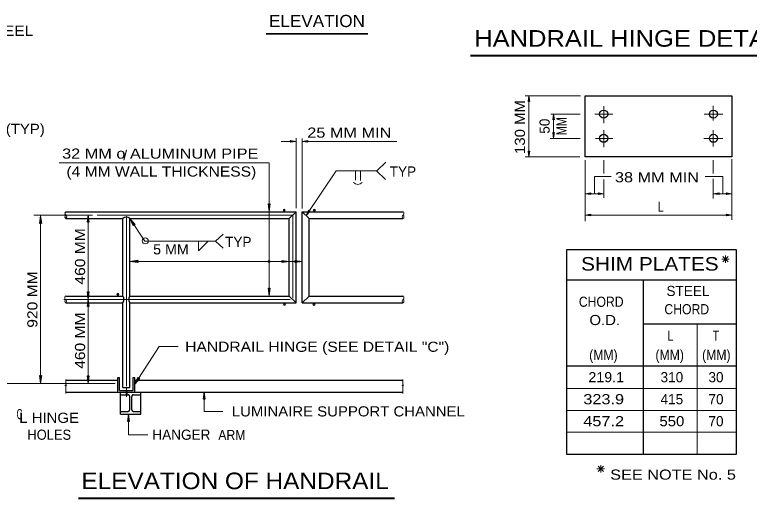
# Model space of a CAD drawing. Extents: x 312601.858 to 312602.699, y 144420.109 to 144420.704.
# Drawn here: x 312602.2633 to 312602.4805, y 144420.41 to 144420.553 of the extents above; entities that cross this region are included whole.
import ezdxf
from ezdxf.enums import TextEntityAlignment as Align

# ---------------------------------------------------------------- set-up
doc = ezdxf.new("R2010")
doc.units = 0
doc.header["$LTSCALE"] = 0.0012
doc.header["$PDMODE"] = 32
doc.header["$PDSIZE"] = 0.0006
doc.linetypes.add('DOT_DASHED', pattern=[7.7, 5, -1.2, 0.3, -1.2])
doc.linetypes.add('MEDIUM_DASHED', pattern=[4.5, 3, -1.5])
for name, color, linetype, lineweight in [('1', 7, 'Continuous', 13), ('2', 7, 'Continuous', 13), ('39', 7, 'Continuous', 13)]:
    doc.layers.add(name, color=color, linetype=linetype, lineweight=lineweight)

msp = doc.modelspace()

# ---------------------------------------------------------------- hatches: boundary and pattern name
at = {"layer": '2'}
msp.add_hatch(color=256, dxfattribs=at).paths.add_polyline_path([(312602.3388, 144420.48, 1), (312602.3382, 144420.48, 1)])
at = {"layer": '39'}
for points in [[(312602.4153, 144420.5275), (312602.4151, 144420.5273), (312602.4153, 144420.529), (312602.4156, 144420.5273)], [(312602.4153, 144420.5275), (312602.4151, 144420.5273), (312602.4153, 144420.529), (312602.4156, 144420.5273)], [(312602.4226, 144420.5221), (312602.4224, 144420.5219), (312602.4226, 144420.5236), (312602.4229, 144420.5219)], [(312602.4226, 144420.518), (312602.4229, 144420.5181), (312602.4226, 144420.5164), (312602.4224, 144420.5181)], [(312602.4226, 144420.518), (312602.4229, 144420.5181), (312602.4226, 144420.5164), (312602.4224, 144420.5181)], [(312602.345, 144420.5155), (312602.3448, 144420.5158), (312602.3465, 144420.5155), (312602.3448, 144420.5153)], [(312602.3499, 144420.5155), (312602.35, 144420.5153), (312602.3483, 144420.5155), (312602.35, 144420.5158)], [(312602.4153, 144420.5125), (312602.4156, 144420.5126), (312602.4153, 144420.5109), (312602.4151, 144420.5126)], [(312602.4153, 144420.5125), (312602.4156, 144420.5126), (312602.4153, 144420.5109), (312602.4151, 144420.5126)], [(312602.4336, 144420.5), (312602.4337, 144420.4998), (312602.432, 144420.5), (312602.4337, 144420.5003)], [(312602.436, 144420.5), (312602.4358, 144420.5003), (312602.4375, 144420.5), (312602.4358, 144420.4998)], [(312602.436, 144420.5), (312602.4358, 144420.5003), (312602.4375, 144420.5), (312602.4358, 144420.4998)], [(312602.4715, 144420.5), (312602.4716, 144420.4998), (312602.4699, 144420.5), (312602.4716, 144420.5003)], [(312602.4739, 144420.5), (312602.4737, 144420.5003), (312602.4754, 144420.5), (312602.4737, 144420.4998)], [(312602.3504, 144420.4949), (312602.3507, 144420.4949), (312602.3495, 144420.4936), (312602.3502, 144420.4952)], [(312602.2709, 144420.4914), (312602.2706, 144420.4912), (312602.2709, 144420.4936), (312602.2713, 144420.4912)], [(312602.2709, 144420.4914), (312602.2706, 144420.4912), (312602.2709, 144420.4936), (312602.2713, 144420.4912)], [(312602.2985, 144420.4909), (312602.2983, 144420.4905), (312602.2973, 144420.4927), (312602.2989, 144420.4909)], [(312602.4336, 144420.4937), (312602.4337, 144420.4935), (312602.432, 144420.4937), (312602.4337, 144420.494)], [(312602.4739, 144420.4937), (312602.4737, 144420.494), (312602.4754, 144420.4937), (312602.4737, 144420.4935)], [(312602.2995, 144420.48), (312602.2997, 144420.4797), (312602.2973, 144420.48), (312602.2997, 144420.4804)], [(312602.2996, 144420.48), (312602.2998, 144420.4797), (312602.2974, 144420.48), (312602.2998, 144420.4804)], [(312602.2709, 144420.4461), (312602.2713, 144420.4463), (312602.2709, 144420.4439), (312602.2706, 144420.4463)]]:
    msp.add_hatch(color=256, dxfattribs=at).paths.add_polyline_path(points)

# ---------------------------------------------------------------- linework, layer by layer
at = {"layer": '1'}
for p, q in [((312602.4143, 144420.529), (312602.4306, 144420.529)), ((312602.4153, 144420.529), (312602.4153, 144420.5109)), ((312602.4218, 144420.5236), (312602.4305, 144420.5236)), ((312602.4226, 144420.5236), (312602.4226, 144420.5164)), ((312602.3465, 144420.4958), (312602.3465, 144420.5165)), ((312602.3483, 144420.4957), (312602.3483, 144420.5164)), ((312602.4217, 144420.5164), (312602.4305, 144420.5164)), ((312602.3421, 144420.5155), (312602.3465, 144420.5155)), ((312602.3483, 144420.5155), (312602.3763, 144420.5155)), ((312602.4304, 144420.5109), (312602.4143, 144420.5109)), ((312602.432, 144420.4919), (312602.432, 144420.51)), ((312602.4375, 144420.51), (312602.4375, 144420.506)), ((312602.4699, 144420.51), (312602.4699, 144420.506)), ((312602.4754, 144420.5102), (312602.4754, 144420.4923)), ((312602.2764, 144420.5092), (312602.3385, 144420.5092)), ((312602.3385, 144420.5092), (312602.3385, 144420.4947)), ((312602.3641, 144420.504), (312602.3641, 144420.5068)), ((312602.3656, 144420.5039), (312602.3656, 144420.5068)), ((312602.4375, 144420.5042), (312602.4375, 144420.4988)), ((312602.4699, 144420.5044), (312602.4699, 144420.4986)), ((312602.432, 144420.5), (312602.4375, 144420.5)), ((312602.4699, 144420.5), (312602.4754, 144420.5)), ((312602.3385, 144420.4947), (312602.3385, 144420.4698)), ((312602.2689, 144420.4937), (312602.2863, 144420.4937)), ((312602.2709, 144420.4936), (312602.2709, 144420.4439)), ((312602.285, 144420.4937), (312602.285, 144420.4439)), ((312602.432, 144420.4937), (312602.4754, 144420.4937)), ((312602.4651, 144420.4616), (312602.4651, 144420.4229)), ((312602.2988, 144420.4437), (312602.306, 144420.4549)), ((312602.306, 144420.4549), (312602.3116, 144420.4549)), ((312602.254, 144420.4439), (312602.293, 144420.4439)), ((312602.4767, 144420.4425), (312602.4266, 144420.4425)), ((312602.2969, 144420.4349), (312602.2969, 144420.4288)), ((312602.4767, 144420.436), (312602.4266, 144420.436)), ((312602.4767, 144420.4295), (312602.4266, 144420.4295)), ((312602.3027, 144420.4288), (312602.2969, 144420.4288))]:
    msp.add_line(p, q, dxfattribs=at)
at = {"layer": '1', "lineweight": 25}
for p, q in [((312602.432, 144420.529), (312602.4754, 144420.529)), ((312602.432, 144420.5109), (312602.432, 144420.529)), ((312602.4754, 144420.529), (312602.4754, 144420.5109)), ((312602.4754, 144420.5109), (312602.432, 144420.5109)), ((312602.2784, 144420.4947), (312602.2938, 144420.4947)), ((312602.2937, 144420.4947), (312602.3465, 144420.4947)), ((312602.3465, 144420.4678), (312602.3465, 144420.4947)), ((312602.3483, 144420.4947), (312602.3781, 144420.4947)), ((312602.3483, 144420.4678), (312602.3483, 144420.4947)), ((312602.2784, 144420.4927), (312602.2953, 144420.4927)), ((312602.2953, 144420.4698), (312602.2953, 144420.4927)), ((312602.2973, 144420.4927), (312602.3445, 144420.4927)), ((312602.2973, 144420.4698), (312602.2973, 144420.4927)), ((312602.3445, 144420.4698), (312602.3445, 144420.4927)), ((312602.3504, 144420.4927), (312602.3781, 144420.4927)), ((312602.3504, 144420.4698), (312602.3504, 144420.4927)), ((312602.4266, 144420.4835), (312602.4767, 144420.4835)), ((312602.4266, 144420.4229), (312602.4266, 144420.4835)), ((312602.4266, 144420.4746), (312602.4767, 144420.4746)), ((312602.4492, 144420.4746), (312602.4492, 144420.4229)), ((312602.2784, 144420.4698), (312602.2953, 144420.4698)), ((312602.2973, 144420.4698), (312602.3445, 144420.4698)), ((312602.3504, 144420.4698), (312602.3781, 144420.4698)), ((312602.2784, 144420.4678), (312602.2953, 144420.4678)), ((312602.2953, 144420.4428), (312602.2953, 144420.4678)), ((312602.2973, 144420.4678), (312602.3465, 144420.4678)), ((312602.2973, 144420.4428), (312602.2973, 144420.4678)), ((312602.3483, 144420.4678), (312602.3781, 144420.4678)), ((312602.4492, 144420.4616), (312602.4767, 144420.4616)), ((312602.4266, 144420.4492), (312602.4767, 144420.4492)), ((312602.2784, 144420.4449), (312602.2938, 144420.4449)), ((312602.2938, 144420.4457), (312602.2943, 144420.4457)), ((312602.2938, 144420.4414), (312602.2938, 144420.4457)), ((312602.2943, 144420.4419), (312602.2943, 144420.4457)), ((312602.2983, 144420.4457), (312602.2988, 144420.4457)), ((312602.2983, 144420.4419), (312602.2983, 144420.4457)), ((312602.2988, 144420.4414), (312602.2988, 144420.4457)), ((312602.2988, 144420.4449), (312602.3781, 144420.4449)), ((312602.2953, 144420.4428), (312602.2973, 144420.4428)), ((312602.2784, 144420.4414), (312602.2998, 144420.4414)), ((312602.2943, 144420.4419), (312602.2983, 144420.4419)), ((312602.2946, 144420.4349), (312602.2946, 144420.4414)), ((312602.2962, 144420.4419), (312602.2962, 144420.4406)), ((312602.2964, 144420.4419), (312602.2964, 144420.4406)), ((312602.2998, 144420.4414), (312602.3781, 144420.4414)), ((312602.3006, 144420.4349), (312602.3006, 144420.4414)), ((312602.2946, 144420.4349), (312602.3006, 144420.4349))]:
    msp.add_line(p, q, dxfattribs=at)
at = {"layer": '1', "linetype": 'DOT_DASHED'}
for p, q in [((312602.4375, 144420.5209), (312602.4375, 144420.5259)), ((312602.4699, 144420.5217), (312602.4699, 144420.526)), ((312602.4349, 144420.5236), (312602.4402, 144420.5236)), ((312602.4727, 144420.5236), (312602.4672, 144420.5236)), ((312602.4375, 144420.5188), (312602.4375, 144420.5138)), ((312602.4699, 144420.5188), (312602.4699, 144420.514)), ((312602.4351, 144420.5164), (312602.4402, 144420.5164)), ((312602.4727, 144420.5164), (312602.4671, 144420.5164)), ((312602.2877, 144420.4937), (312602.3455, 144420.4937)), ((312602.2963, 144420.4934), (312602.2963, 144420.4431)), ((312602.3455, 144420.4936), (312602.3455, 144420.4692)), ((312602.2778, 144420.4688), (312602.3448, 144420.4688)), ((312602.2963, 144420.4425), (312602.2963, 144420.44))]:
    msp.add_line(p, q, dxfattribs=at)
at = {"layer": '1', "linetype": 'MEDIUM_DASHED', "lineweight": 25}
for p, q in [((312602.2946, 144420.4406), (312602.2968, 144420.4406)), ((312602.2984, 144420.4406), (312602.3006, 144420.4406)), ((312602.2973, 144420.4362), (312602.2973, 144420.4401)), ((312602.2979, 144420.4362), (312602.2979, 144420.4401)), ((312602.2946, 144420.4357), (312602.2968, 144420.4357)), ((312602.2984, 144420.4357), (312602.3006, 144420.4357))]:
    msp.add_line(p, q, dxfattribs=at)
at = {"layer": '1'}
for points in [[(312602.3388, 144420.497), (312602.3385, 144420.4947), (312602.3382, 144420.497), (312602.3385, 144420.4967)], [(312602.2847, 144420.4916), (312602.285, 144420.4938), (312602.2853, 144420.4916), (312602.285, 144420.4918)], [(312602.3423, 144420.4803), (312602.3445, 144420.48), (312602.3423, 144420.4797), (312602.3425, 144420.48)], [(312602.3461, 144420.4803), (312602.3483, 144420.48), (312602.3461, 144420.4797), (312602.3463, 144420.48)], [(312602.2853, 144420.471), (312602.285, 144420.4687), (312602.2847, 144420.471), (312602.285, 144420.4707)], [(312602.3388, 144420.4721), (312602.3385, 144420.4698), (312602.3382, 144420.4721), (312602.3385, 144420.4718)], [(312602.2847, 144420.4667), (312602.285, 144420.4689), (312602.2853, 144420.4667), (312602.285, 144420.4669)], [(312602.2853, 144420.4462), (312602.285, 144420.4439), (312602.2847, 144420.4462), (312602.285, 144420.4459)], [(312602.3003, 144420.4454), (312602.2988, 144420.4437), (312602.2997, 144420.4458), (312602.2999, 144420.4454)], [(312602.319, 144420.4393), (312602.3193, 144420.4415), (312602.3196, 144420.4393), (312602.3193, 144420.4395)], [(312602.2966, 144420.4327), (312602.2969, 144420.4349), (312602.2972, 144420.4327), (312602.2969, 144420.4329)]]:
    msp.add_lwpolyline(points, close=True, dxfattribs=at)
at = {"layer": '1', "lineweight": 25}
msp.add_lwpolyline([(312602.4767, 144420.4835), (312602.4767, 144420.4229), (312602.4266, 144420.4229)], dxfattribs=at)
at = {"layer": '1'}
for points in [[(312602.2973, 144420.48), (312602.3445, 144420.48), (312602.3483, 144420.48)], [(312602.2784, 144420.4451), (312602.2784, 144420.4435), (312602.2784, 144420.441)], [(312602.3781, 144420.4451), (312602.3781, 144420.4435), (312602.3781, 144420.441)], [(312602.2784, 144420.4435), (312602.2787, 144420.4434), (312602.2781, 144420.4433), (312602.2784, 144420.4432)], [(312602.3781, 144420.4435), (312602.3784, 144420.4434), (312602.3778, 144420.4433), (312602.3781, 144420.4432)], [(312602.3193, 144420.4414), (312602.3193, 144420.4357), (312602.3248, 144420.4357)]]:
    msp.add_lwpolyline(points, dxfattribs=at)
at = {"layer": '1', "lineweight": 25}
for centre in [(312602.437475, 144420.523555), (312602.469945, 144420.523555), (312602.437475, 144420.516415), (312602.469945, 144420.516415)]:
    msp.add_circle(centre, 0.00119, dxfattribs=at)
at = {"layer": '1', "linetype": 'MEDIUM_DASHED', "lineweight": 25}
for centre, start, end in [((312602.2968, 144420.4401), 0, 90), ((312602.2984, 144420.4401), 90, 180), ((312602.2968, 144420.4362), 270, 0), ((312602.2984, 144420.4362), 180, 270)]:
    msp.add_arc(centre, 0.0005, start, end, dxfattribs=at)
at = {"layer": '1'}
for centre, start_param, end_param in [((312602.378145, 144420.494215), 3.1415927, 6.411123), ((312602.278355, 144420.46931), 6.1552476, 9.424778), ((312602.378145, 144420.46931), 3.1415927, 6.411123)]:
    msp.add_ellipse(centre, major_axis=(0, 0.00051), ratio=0.5, start_param=start_param, end_param=end_param, dxfattribs=at)
for centre in [(312602.378145, 144420.493195), (312602.278355, 144420.46829), (312602.378145, 144420.46829)]:
    msp.add_ellipse(centre, major_axis=(0, 0.00051), ratio=0.5, dxfattribs=at)
for p in [(312602.343, 144420.4952), (312602.3519, 144420.4952), (312602.2938, 144420.4703), (312602.3431, 144420.4673), (312602.3518, 144420.4673)]:
    msp.add_point(p, dxfattribs=at)
at = {"layer": '2', "lineweight": 35}
msp.add_line((312602.3377, 144420.5473), (312602.3677, 144420.5473), dxfattribs=at)
at = {"layer": '2', "lineweight": 40}
for p, q in [((312602.3981, 144420.5409), (312602.5063, 144420.5409)), ((312602.2821, 144420.41), (312602.3756, 144420.41))]:
    msp.add_line(p, q, dxfattribs=at)
at = {"layer": '2'}
for p, q in [((312602.3704, 144420.5068), (312602.373, 144420.5094)), ((312602.3703, 144420.5068), (312602.3729, 144420.5042)), ((312602.4348, 144420.5051), (312602.4397, 144420.5051)), ((312602.4348, 144420.5), (312602.4348, 144420.5051)), ((312602.4675, 144420.5051), (312602.4727, 144420.5051)), ((312602.4727, 144420.5), (312602.4727, 144420.5051)), ((312602.3227, 144420.486), (312602.3249, 144420.4881)), ((312602.3227, 144420.486), (312602.3249, 144420.4839)), ((312602.4735, 144420.4806), (312602.4735, 144420.4818)), ((312602.4736, 144420.4807), (312602.4724, 144420.4807)), ((312602.4736, 144420.4806), (312602.4727, 144420.4815)), ((312602.4736, 144420.4808), (312602.4727, 144420.4799)), ((312602.4734, 144420.4806), (312602.4743, 144420.4815)), ((312602.4734, 144420.4808), (312602.4743, 144420.4799)), ((312602.4734, 144420.4807), (312602.4746, 144420.4807)), ((312602.4735, 144420.4808), (312602.4735, 144420.4796)), ((312602.4367, 144420.4187), (312602.4355, 144420.4187)), ((312602.4367, 144420.4186), (312602.4358, 144420.4195)), ((312602.4367, 144420.4188), (312602.4358, 144420.4179)), ((312602.4365, 144420.4186), (312602.4374, 144420.4195)), ((312602.4365, 144420.4188), (312602.4374, 144420.4179)), ((312602.4365, 144420.4187), (312602.4377, 144420.4187)), ((312602.4366, 144420.4186), (312602.4366, 144420.4198)), ((312602.4366, 144420.4186), (312602.4366, 144420.4198)), ((312602.4366, 144420.4188), (312602.4366, 144420.4176))]:
    msp.add_line(p, q, dxfattribs=at)
at = {"layer": '2', "lineweight": 25}
for p, q in [((312602.3445, 144420.4927), (312602.3465, 144420.4947)), ((312602.3504, 144420.4927), (312602.3483, 144420.4947)), ((312602.3465, 144420.4678), (312602.3445, 144420.4698)), ((312602.3483, 144420.4678), (312602.3504, 144420.4698))]:
    msp.add_line(p, q, dxfattribs=at)
at = {"layer": '2'}
for points in [[(312602.3495, 144420.4936), (312602.3584, 144420.5068), (312602.3704, 144420.5068)], [(312602.2973, 144420.4927), (312602.3018, 144420.486), (312602.3228, 144420.486)], [(312602.3176, 144420.486), (312602.3176, 144420.4832), (312602.3204, 144420.4859)]]:
    msp.add_lwpolyline(points, dxfattribs=at)
for centre, radius in [((312602.3019, 144420.4861), 0.0009), ((312602.3385, 144420.48), 0.0003)]:
    msp.add_circle(centre, radius, dxfattribs=at)
at = {"layer": '2', "lineweight": 25}
for centre, radius, start, end in [((312602.27865, 144420.4942), 0.000559, 116.56505, 243.43495), ((312602.27865, 144420.4932), 0.000559, 116.56505, 243.43495), ((312602.27815, 144420.4932), 0.000559, 296.56505, 63.43495), ((312602.2963, 144420.49165), 0.00145, 46.39718, 133.60282), ((312602.293783, 144420.4688), 0.001817, 326.60151, 33.39849), ((312602.298817, 144420.4688), 0.001817, 146.60151, 213.39849)]:
    msp.add_arc(centre, radius, start, end, dxfattribs=at)
at = {"layer": '2'}
msp.add_ellipse((312602.3648, 144420.504617), major_axis=(-0.001, -0.001517), ratio=0.983756, start_param=6.0844512, end_param=7.6472927, dxfattribs=at)
at = {"layer": '39'}
for points in [[(312602.4153, 144420.5275), (312602.4151, 144420.5273), (312602.4153, 144420.529), (312602.4156, 144420.5273)], [(312602.4153, 144420.5275), (312602.4151, 144420.5273), (312602.4153, 144420.529), (312602.4156, 144420.5273)], [(312602.4226, 144420.5221), (312602.4224, 144420.5219), (312602.4226, 144420.5236), (312602.4229, 144420.5219)], [(312602.4226, 144420.518), (312602.4229, 144420.5181), (312602.4226, 144420.5164), (312602.4224, 144420.5181)], [(312602.4226, 144420.518), (312602.4229, 144420.5181), (312602.4226, 144420.5164), (312602.4224, 144420.5181)], [(312602.345, 144420.5155), (312602.3448, 144420.5158), (312602.3465, 144420.5155), (312602.3448, 144420.5153)], [(312602.3499, 144420.5155), (312602.35, 144420.5153), (312602.3483, 144420.5155), (312602.35, 144420.5158)], [(312602.4153, 144420.5125), (312602.4156, 144420.5126), (312602.4153, 144420.5109), (312602.4151, 144420.5126)], [(312602.4153, 144420.5125), (312602.4156, 144420.5126), (312602.4153, 144420.5109), (312602.4151, 144420.5126)], [(312602.4336, 144420.5), (312602.4337, 144420.4998), (312602.432, 144420.5), (312602.4337, 144420.5003)], [(312602.436, 144420.5), (312602.4358, 144420.5003), (312602.4375, 144420.5), (312602.4358, 144420.4998)], [(312602.436, 144420.5), (312602.4358, 144420.5003), (312602.4375, 144420.5), (312602.4358, 144420.4998)], [(312602.4715, 144420.5), (312602.4716, 144420.4998), (312602.4699, 144420.5), (312602.4716, 144420.5003)], [(312602.4739, 144420.5), (312602.4737, 144420.5003), (312602.4754, 144420.5), (312602.4737, 144420.4998)], [(312602.3504, 144420.4949), (312602.3507, 144420.4949), (312602.3495, 144420.4936), (312602.3502, 144420.4952)], [(312602.2709, 144420.4914), (312602.2706, 144420.4912), (312602.2709, 144420.4936), (312602.2713, 144420.4912)], [(312602.2709, 144420.4914), (312602.2706, 144420.4912), (312602.2709, 144420.4936), (312602.2713, 144420.4912)], [(312602.2985, 144420.4909), (312602.2983, 144420.4905), (312602.2973, 144420.4927), (312602.2989, 144420.4909)], [(312602.4336, 144420.4937), (312602.4337, 144420.4935), (312602.432, 144420.4937), (312602.4337, 144420.494)], [(312602.4739, 144420.4937), (312602.4737, 144420.494), (312602.4754, 144420.4937), (312602.4737, 144420.4935)], [(312602.2995, 144420.48), (312602.2997, 144420.4797), (312602.2973, 144420.48), (312602.2997, 144420.4804)], [(312602.2996, 144420.48), (312602.2998, 144420.4797), (312602.2974, 144420.48), (312602.2998, 144420.4804)], [(312602.2709, 144420.4461), (312602.2713, 144420.4463), (312602.2709, 144420.4439), (312602.2706, 144420.4463)]]:
    msp.add_lwpolyline(points, close=True, dxfattribs=at)

# ---------------------------------------------------------------- texts
at = {"layer": '2'}
for s, height, width, p in [('ELEVATION', 0.0036, 1.05, (312602.3385, 144420.5493)), ('STAINLESS STEEL', 0.003, 1.15, (312602.2275, 144420.5467)), ('HANDRAIL HINGE DETAIL "C"', 0.0049, 1.15, (312602.3992, 144420.5435)), ('32 MM o ALUMINUM PIPE', 0.003, 1.2, (312602.2773, 144420.5104)), ('SHIM PLATES', 0.004, 1.15, (312602.4308, 144420.4773)), ('L', 0.003, 0.75, (312602.4564, 144420.4566)), ('T', 0.003, 0.8, (312602.4697, 144420.4566)), ('HANDRAIL HINGE (SEE DETAIL "C")', 0.003, 1.15, (312602.3137, 144420.4533)), ('LUMINAIRE SUPPORT CHANNEL', 0.003, 1.1, (312602.3275, 144420.4342)), ('ARM', 0.003, 0.9, (312602.3235, 144420.4272)), ('ELEVATION OF HANDRAIL', 0.0049, 1.1, (312602.283, 144420.4127)), ('SEE NOTE No. 5', 0.003, 1.2, (312602.4394, 144420.4155))]:
    msp.add_text(s, height=height, dxfattribs=dict(at, width=width)).set_placement(p)
for s, width, p in [('130 MM', 1.1, (312602.4142, 144420.51975)), ('MM', 0.8, (312602.4265, 144420.52)), ('460 MM', 1.15, (312602.2841, 144420.4815)), ('920 MM', 1.15, (312602.27, 144420.46875)), ('460 MM', 1.15, (312602.2841, 144420.4566))]:
    msp.add_text(s, height=0.003, rotation=90, dxfattribs=dict(at, width=width)).set_placement(p, align=Align.CENTER)
for s, width, p in [('SIGN HANGER (TYP)', 1.1, (312602.25035, 144420.5177)), ('25 MM MIN', 1.2, (312602.36225, 144420.5166)), ('(4 MM WALL THICKNESS)', 1.15, (312602.30665, 144420.5051)), ('38 MM MIN', 1.2, (312602.45325, 144420.5034)), ('L', 0.75, (312602.45435, 144420.4947)), ('5 MM', 1.05, (312602.3095, 144420.4821)), ('CHORD', 0.9, (312602.43675, 144420.4666)), ('CHORD', 0.9, (312602.46205, 144420.4644)), ('O.D.', 1.1, (312602.4378, 144420.4612)), ('(MM)', 0.9, (312602.4374, 144420.4509)), ('(MM)', 0.9, (312602.457, 144420.4509)), ('(MM)', 0.9, (312602.4708, 144420.4509)), ('C', 0.6, (312602.2647, 144420.4334)), ('L HINGE', 1.1, (312602.27345, 144420.4323)), ('550', 1.1, (312602.45765, 144420.4313)), ('HOLES', 0.95, (312602.2735, 144420.4273))]:
    msp.add_text(s, height=0.003, dxfattribs=dict(at, width=width)).set_placement(p, align=Align.CENTER)
msp.add_text('50', height=0.003, rotation=90, dxfattribs=at).set_placement((312602.4215, 144420.52), align=Align.CENTER)
for s, p in [('/', (312602.29595, 144420.5099)), ('TYP', (312602.3781, 144420.5051)), ('TYP', (312602.3294, 144420.4843)), ('STEEL', (312602.4624, 144420.4698)), ('310', (312602.45765, 144420.4443)), ('30', (312602.4707, 144420.4443)), ('415', (312602.45765, 144420.4378)), ('70', (312602.4707, 144420.4378)), ('70', (312602.4707, 144420.4313))]:
    msp.add_text(s, height=0.003, dxfattribs=at).set_placement(p, align=Align.CENTER)
for s, width, p in [('219.1', 1.05, (312602.4435, 144420.4443)), ('323.9', 1.2, (312602.4435, 144420.4378)), ('457.2', 1.2, (312602.4435, 144420.4313))]:
    msp.add_text(s, height=0.003, dxfattribs=dict(at, width=width)).set_placement(p, align=Align.RIGHT)
msp.add_text('HANGER', height=0.003, dxfattribs=at).set_placement((312602.304, 144420.4273))

doc.saveas('drawing.dxf')
